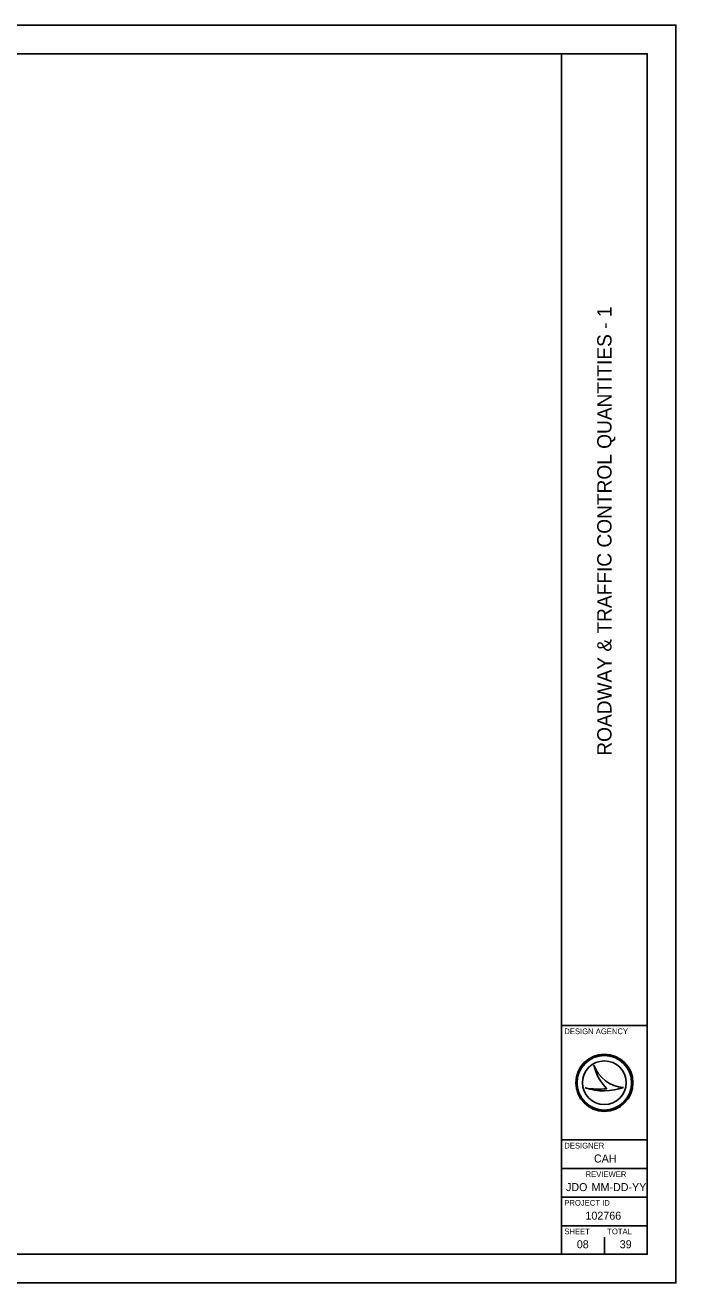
# Model space of a CAD drawing. Extents: x 0 to 34, y 0 to 22.
# Drawn here: x 22.62 to 34, y 0 to 22 of the extents above; entities that cross this region are included whole.
import ezdxf

# ---------------------------------------------------------------- set-up
doc = ezdxf.new("R2010")
doc.units = 0
for name, color, linetype in [('SH_Border', 7, 'Continuous'), ('SH_Cut_Line', 7, 'Continuous'), ('SH_Data', 7, 'Continuous')]:
    doc.layers.add(name, color=color, linetype=linetype)

msp = doc.modelspace()

# ---------------------------------------------------------------- linework, layer by layer
at = {"layer": 'SH_Border'}
for p, q in [((32, 0.5), (32, 21.5)), ((32, 4.5), (33.5, 4.5)), ((32, 2.5), (33.5, 2.5)), ((32, 2), (33.5, 2)), ((32, 1.5), (33.5, 1.5)), ((32, 1), (33.5, 1))]:
    msp.add_line(p, q, dxfattribs=at)
msp.add_lwpolyline([(1.5, 21.5), (33.5, 21.5), (33.5, 0.5), (1.5, 0.5)], close=True, dxfattribs=at)
at = {"layer": 'SH_Cut_Line'}
msp.add_lwpolyline([(0, 0), (34, 0), (34, 22), (0, 22)], close=True, dxfattribs=at)
at = {"layer": 'SH_Data'}
for p, q in [((32.567, 3.81), (32.567, 3.81)), ((32.417, 3.41), (32.417, 3.41)), ((32.75, 3.5), (32.75, 3.5)), ((33.087, 3.419), (33.087, 3.419)), ((32.375, 0.675), (32.375, 0.675)), ((32.75, 0.5), (32.75, 0.8))]:
    msp.add_line(p, q, dxfattribs=at)
for radius in [0.5, 0.477, 0.477, 0.382]:
    msp.add_circle((32.75, 3.5), radius, dxfattribs=at)
for centre, radius, start, end in [((33.116, 3.998), 0.58, 198.9257, 198.9319), ((33.347, 3.97), 0.796, 191.6379, 191.6421), ((33.116, 3.998), 0.58, 198.9319, 267.1657), ((33.347, 3.97), 0.796, 191.6421, 226.0947), ((32.739, 4.37), 1.013, 251.4576, 290.0832), ((32.648, 4.654), 1.266, 259.4964, 259.4995), ((32.739, 4.37), 1.013, 251.4527, 251.4576), ((32.648, 4.654), 1.266, 259.4995, 276.6672)]:
    msp.add_arc(centre, radius, start, end, dxfattribs=at)

# ---------------------------------------------------------------- texts
msp.add_text('ROADWAY & TRAFFIC CONTROL QUANTITIES - 1', height=0.25, rotation=90, dxfattribs=at).set_placement((32.875, 9.221))
for s, height, p in [('DESIGN AGENCY', 0.1, (32.05, 4.35)), ('DESIGNER', 0.1, (32.05, 2.35)), ('CAH', 0.14, (32.568, 2.105)), ('REVIEWER', 0.1, (32.422, 1.85)), ('JDO', 0.14, (32.079, 1.605)), ('MM-DD-YY', 0.14, (32.527, 1.605)), ('PROJECT ID', 0.1, (32.05, 1.35)), ('102766', 0.14, (32.419, 1.105)), ('SHEET', 0.1, (32.05, 0.85)), ('TOTAL', 0.1, (32.8, 0.85)), ('08', 0.14, (32.268, 0.605)), ('39', 0.14, (33.019, 0.605))]:
    msp.add_text(s, height=height, dxfattribs=at).set_placement(p)

doc.saveas('drawing.dxf')
